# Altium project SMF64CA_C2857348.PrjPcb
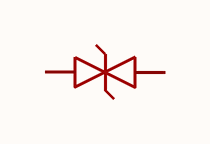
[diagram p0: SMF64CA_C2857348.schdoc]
1 sheet, 1 parts. Net scope: global (net labels, ports and power ports of the same name join across sheets).

## Sheet SMF64CA_C2857348.schdoc
size 127 x 101 mm

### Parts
D?  smf64ca_c2857348  [SOD-123FL_L2.8-W1.8-LS3.7-BI]  (value not drawn)

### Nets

Not connected (* = marked no-connect by the designer): D? 1 2

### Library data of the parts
D? = smf64ca_c2857348: 极性:双向;反向截止电压(Vrwm):64V;钳位电压:103V;峰值脉冲电流(Ipp):1.9A;峰值脉冲功率(Ppp):200W@10/1000us;击穿电压(VBR):71.1V;; Manufacturer: JSMSEMI(杰盛微); AddInBom: yes; ModelId: d105299b3871451c86f679efef28ff8f; ModelTransform: 145.669,70.866,0,0,0,0,0,0,0; Polarity: 双向; Reverse Stand-Off Voltage (Vrwm): 64V; Clamping Voltage: 103V; Peak Pulse Current (Ipp): 1.9A; Voltage - Breakdown: 71.1V; Reverse Leakage Current (Ir): 1uA; Number of Channels: 单路; Type: TVS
